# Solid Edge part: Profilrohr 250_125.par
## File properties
Username: ahadarics
Dokumentum tartalom típus: 0
Author: ahadarics
Last saved by: ahadarics
Revision: 82
Sűrűség: 0,000 kg/m^3
Pontosság: 0,990
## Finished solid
Body 1: solid body, 8 faces, 12 edges, 6 vertices.
  Faces by surface: cone 4, cylinder 2, plane 2
  Edges by curve: circle 8, line 4
Bounding box of the edges (mm): 262.000 x 205.000 x 262.000, from (-131, -152.5, -131) to (131, 52.5, 131).
Cylindrical faces by radius (mm): R125 x1, R131 x1
Conical faces (half-angle, radius in mm at the cone's reference point): 45 deg R125.25 x2, 45 deg R130.9 x2
Planar faces by outward normal: +y 1, -y 1
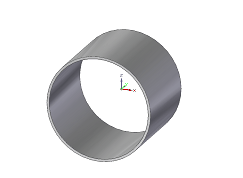
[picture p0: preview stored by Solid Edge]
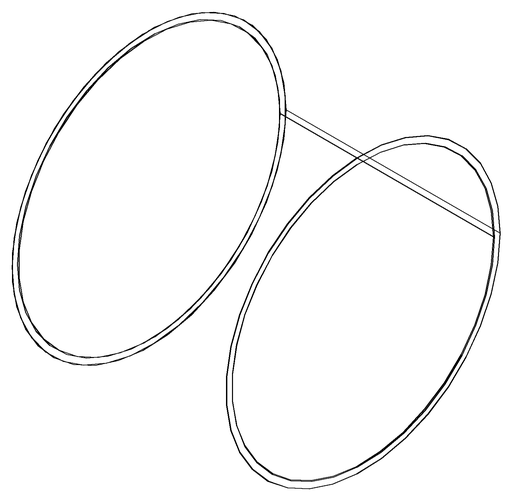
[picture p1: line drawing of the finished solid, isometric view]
